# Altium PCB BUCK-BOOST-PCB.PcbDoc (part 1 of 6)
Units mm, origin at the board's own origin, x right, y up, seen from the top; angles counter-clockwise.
Board outline 99.9 x 67.48 mm, 4 copper layers (Top Layer, POWER, GND, Bottom Layer); 181 components, 110 nets, 560 pads, 389 vias.
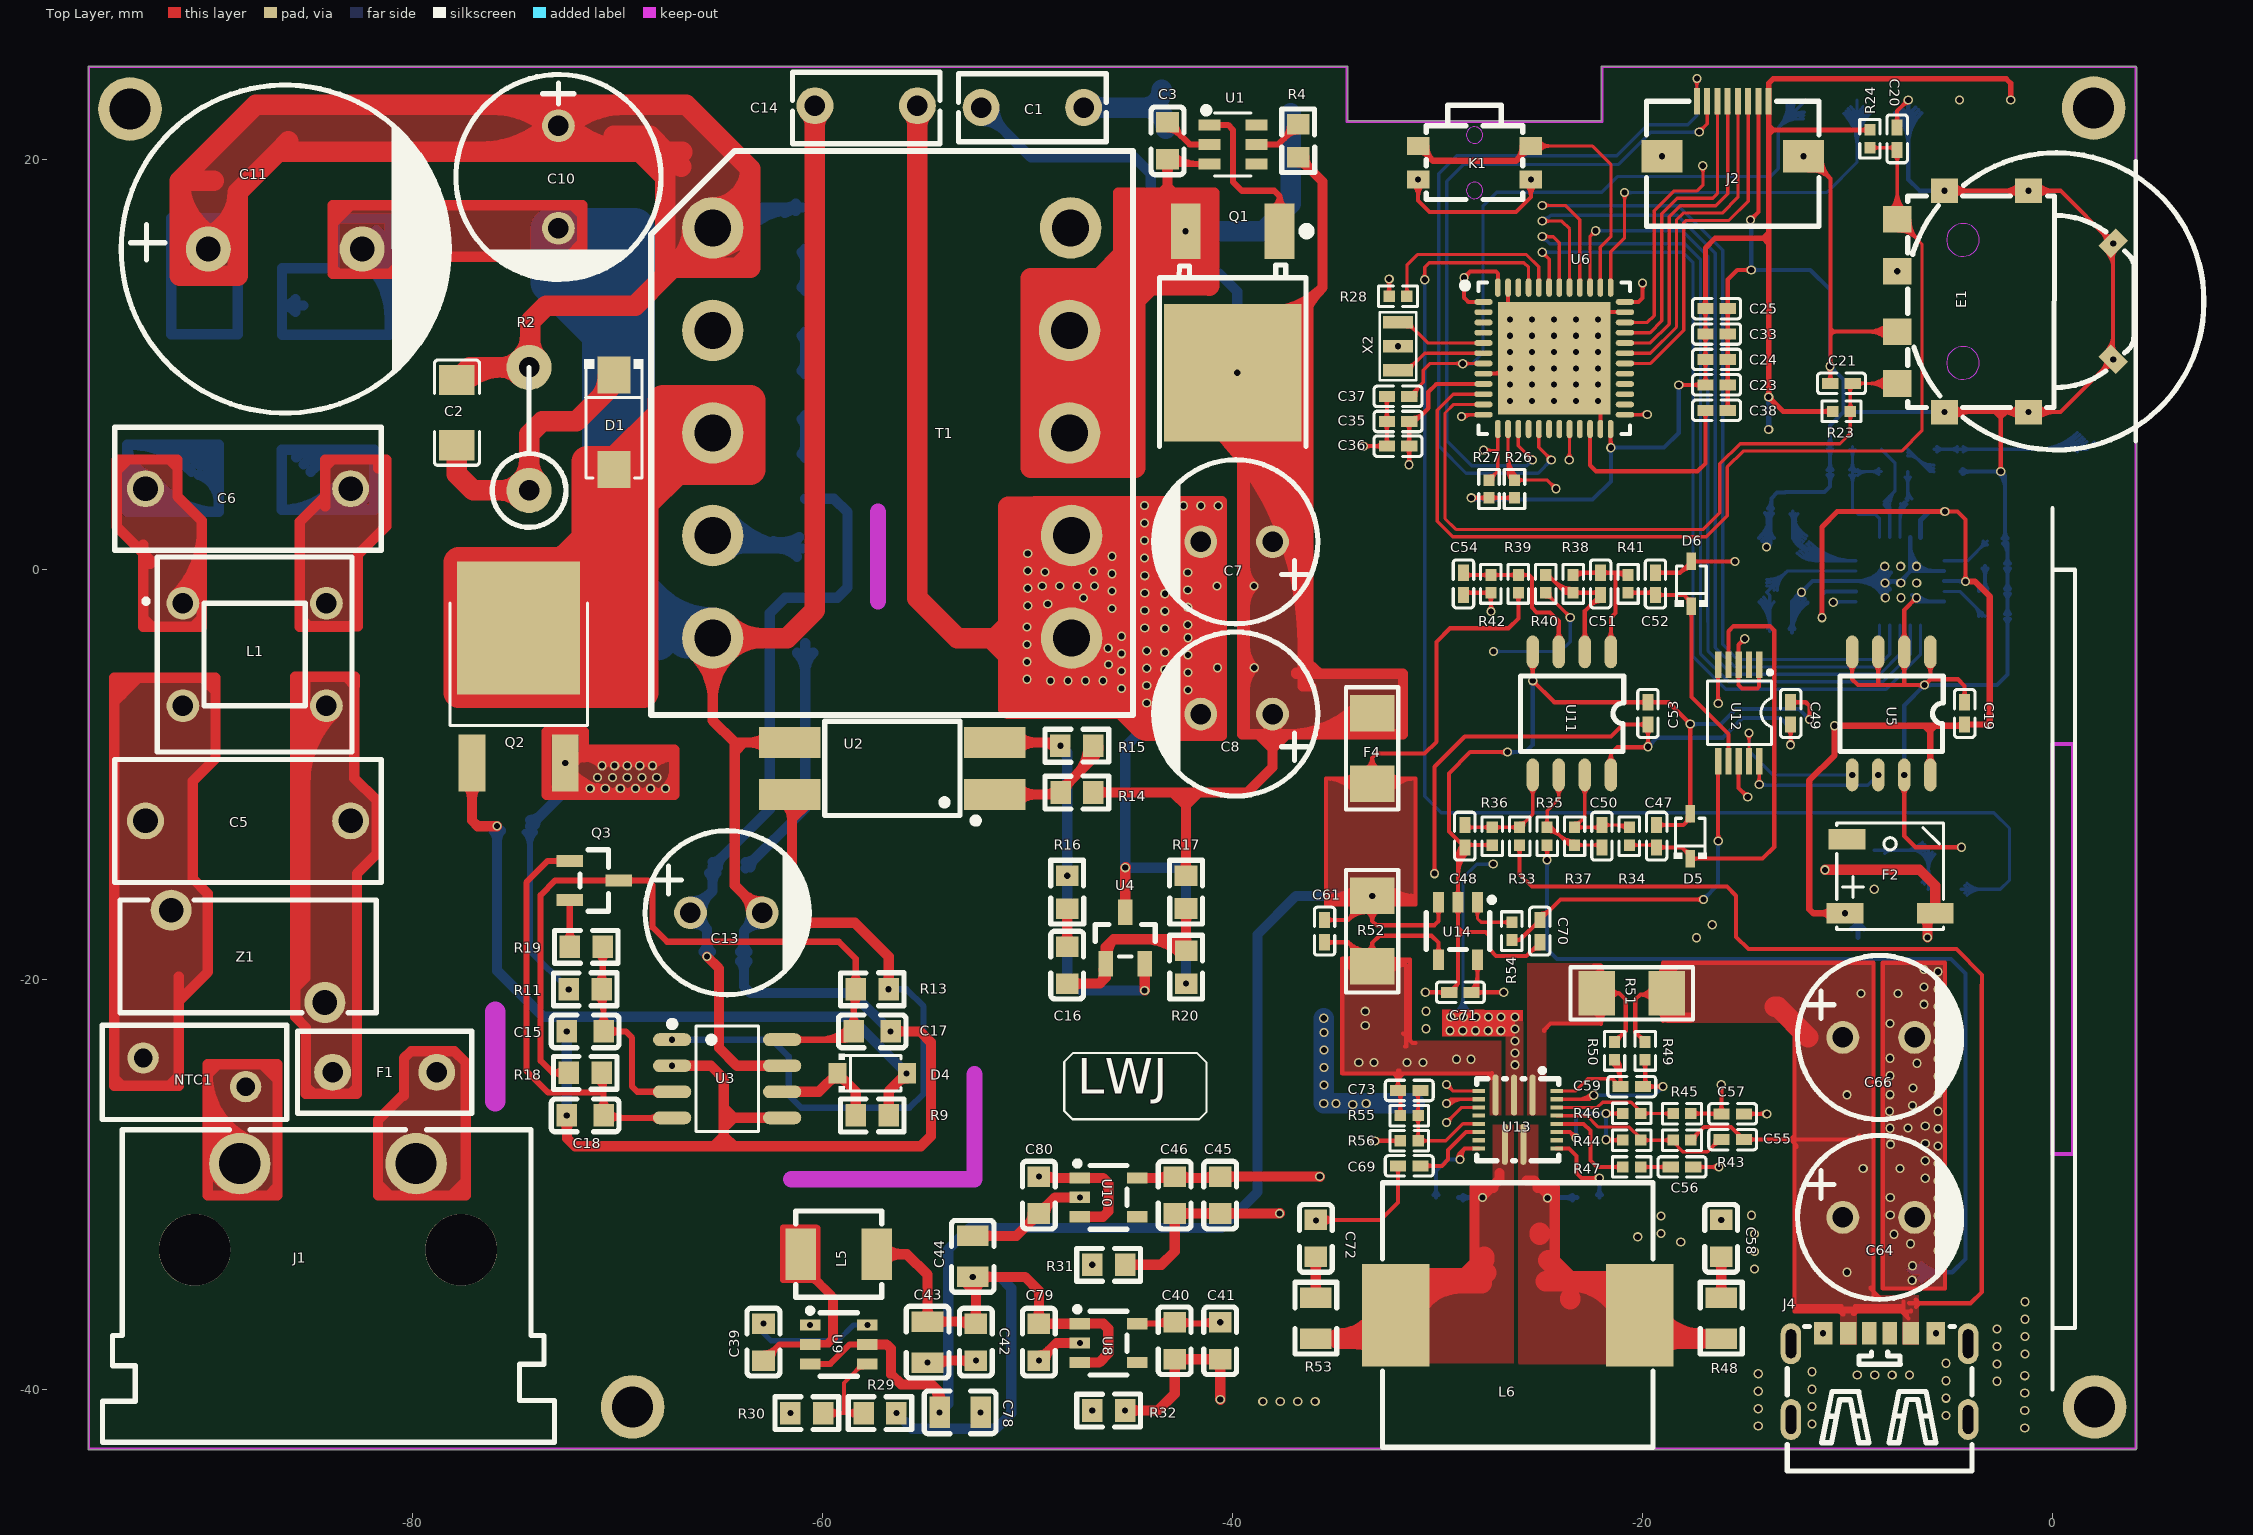
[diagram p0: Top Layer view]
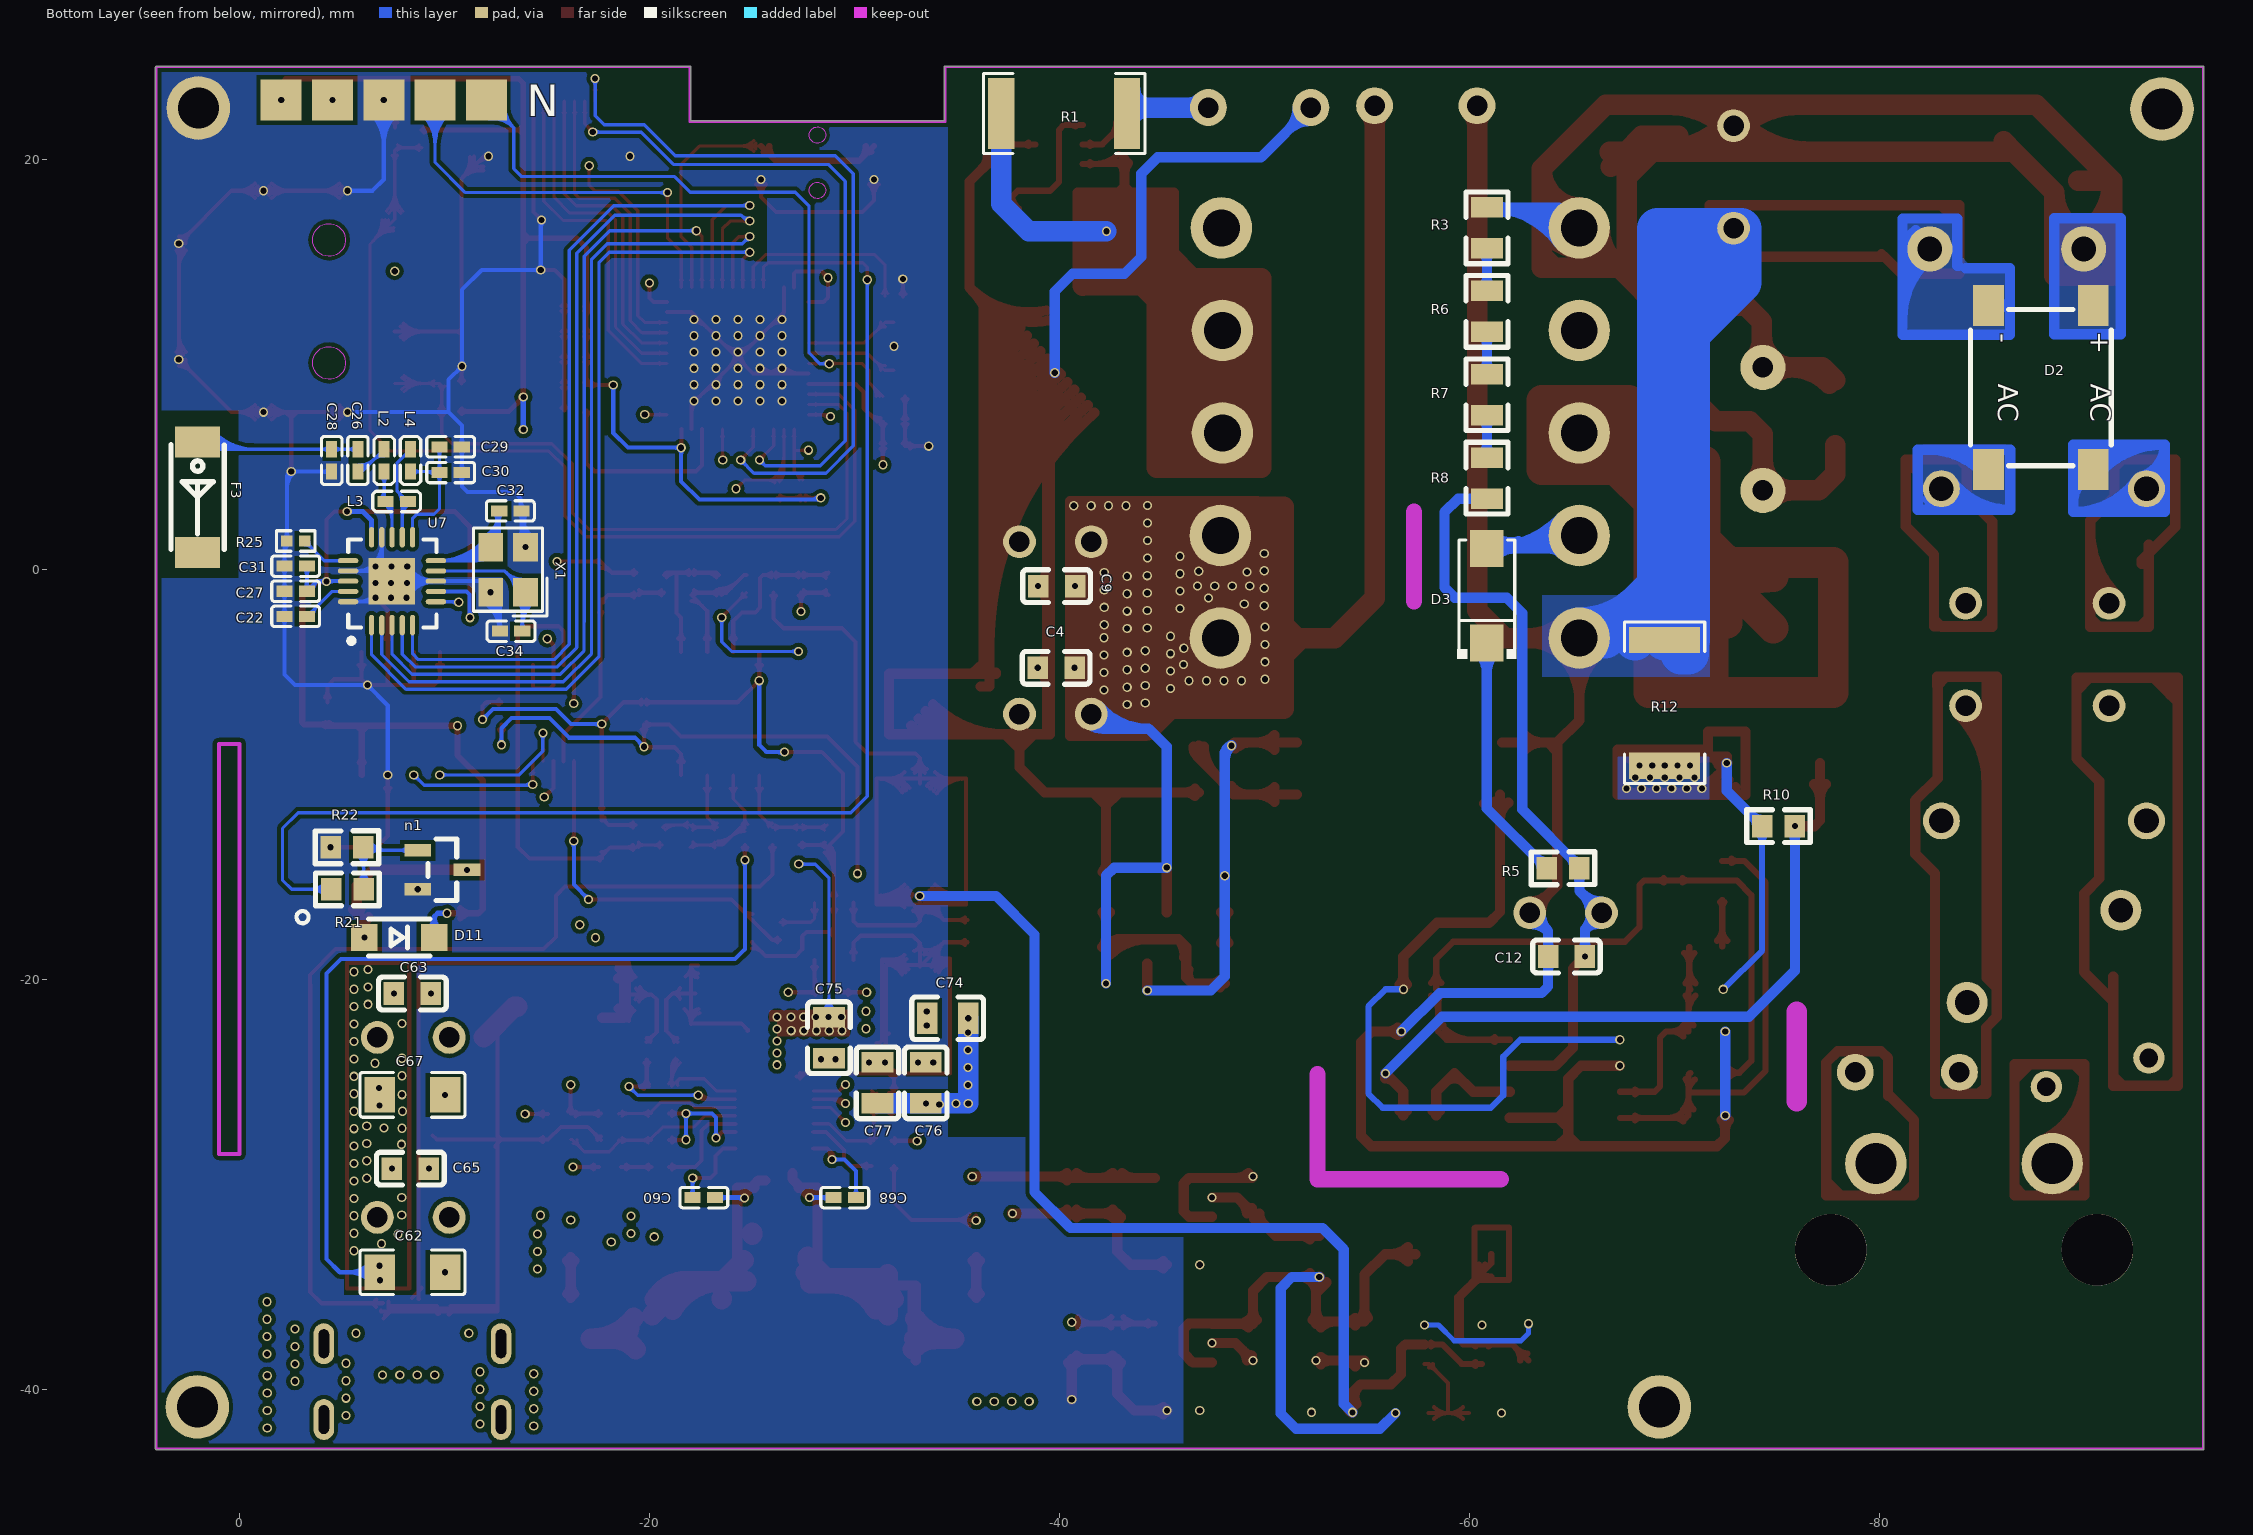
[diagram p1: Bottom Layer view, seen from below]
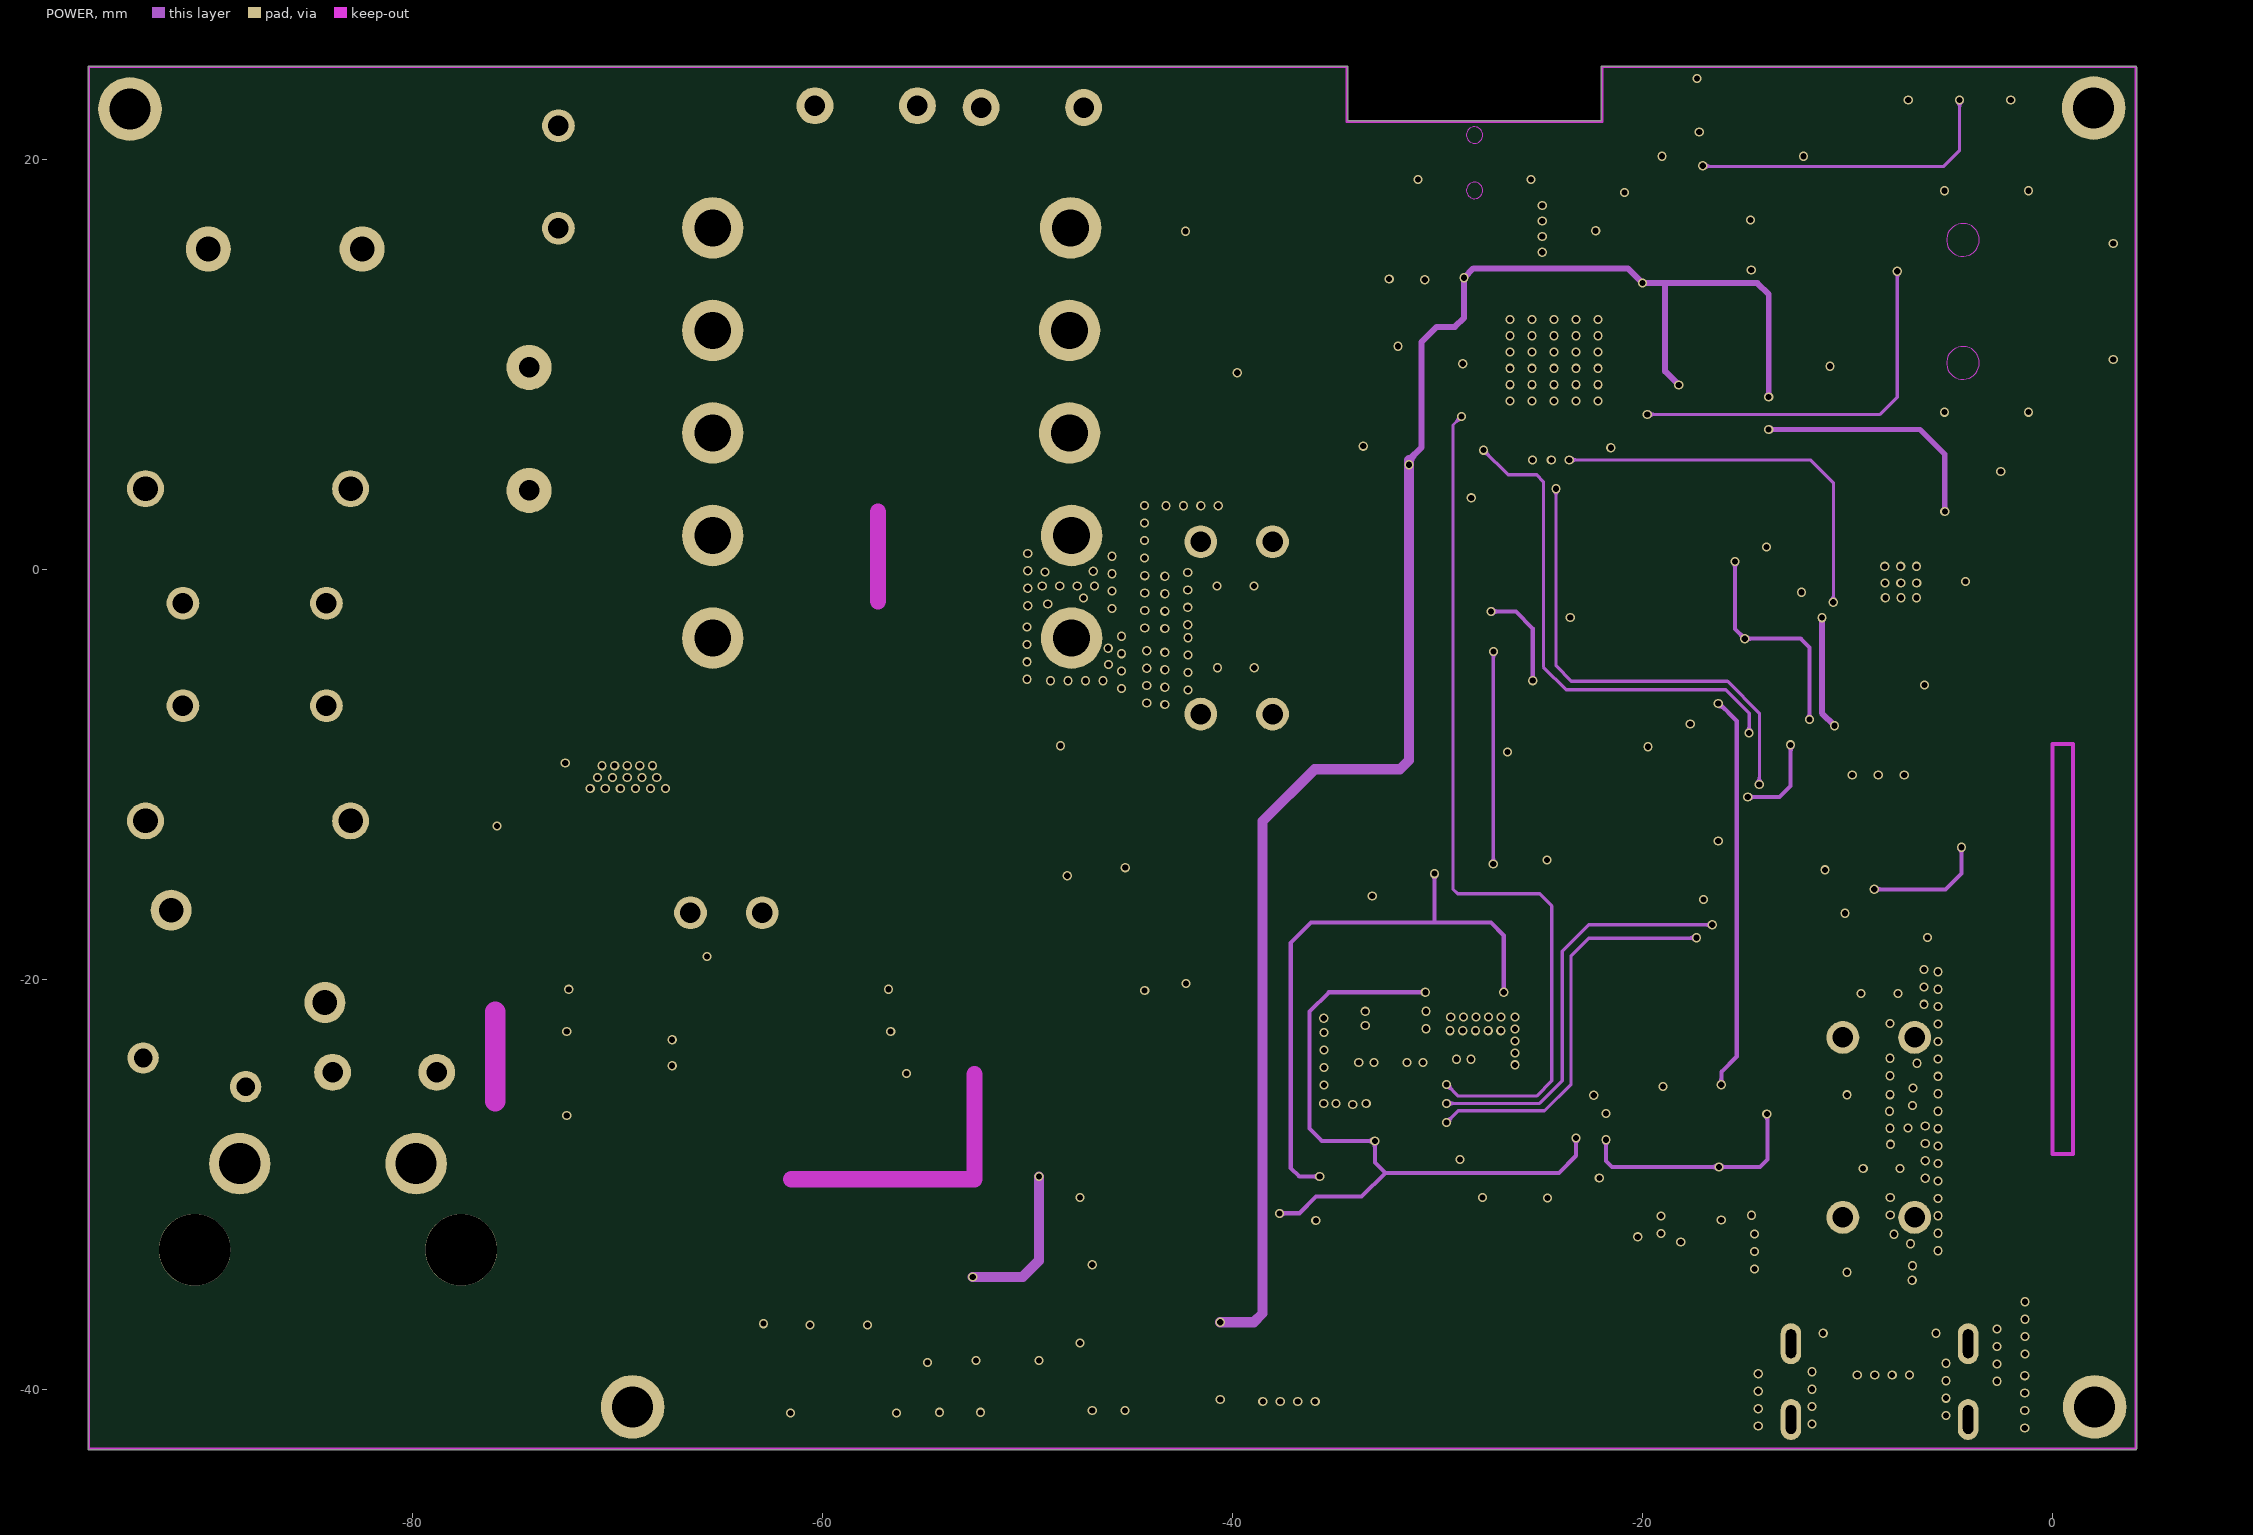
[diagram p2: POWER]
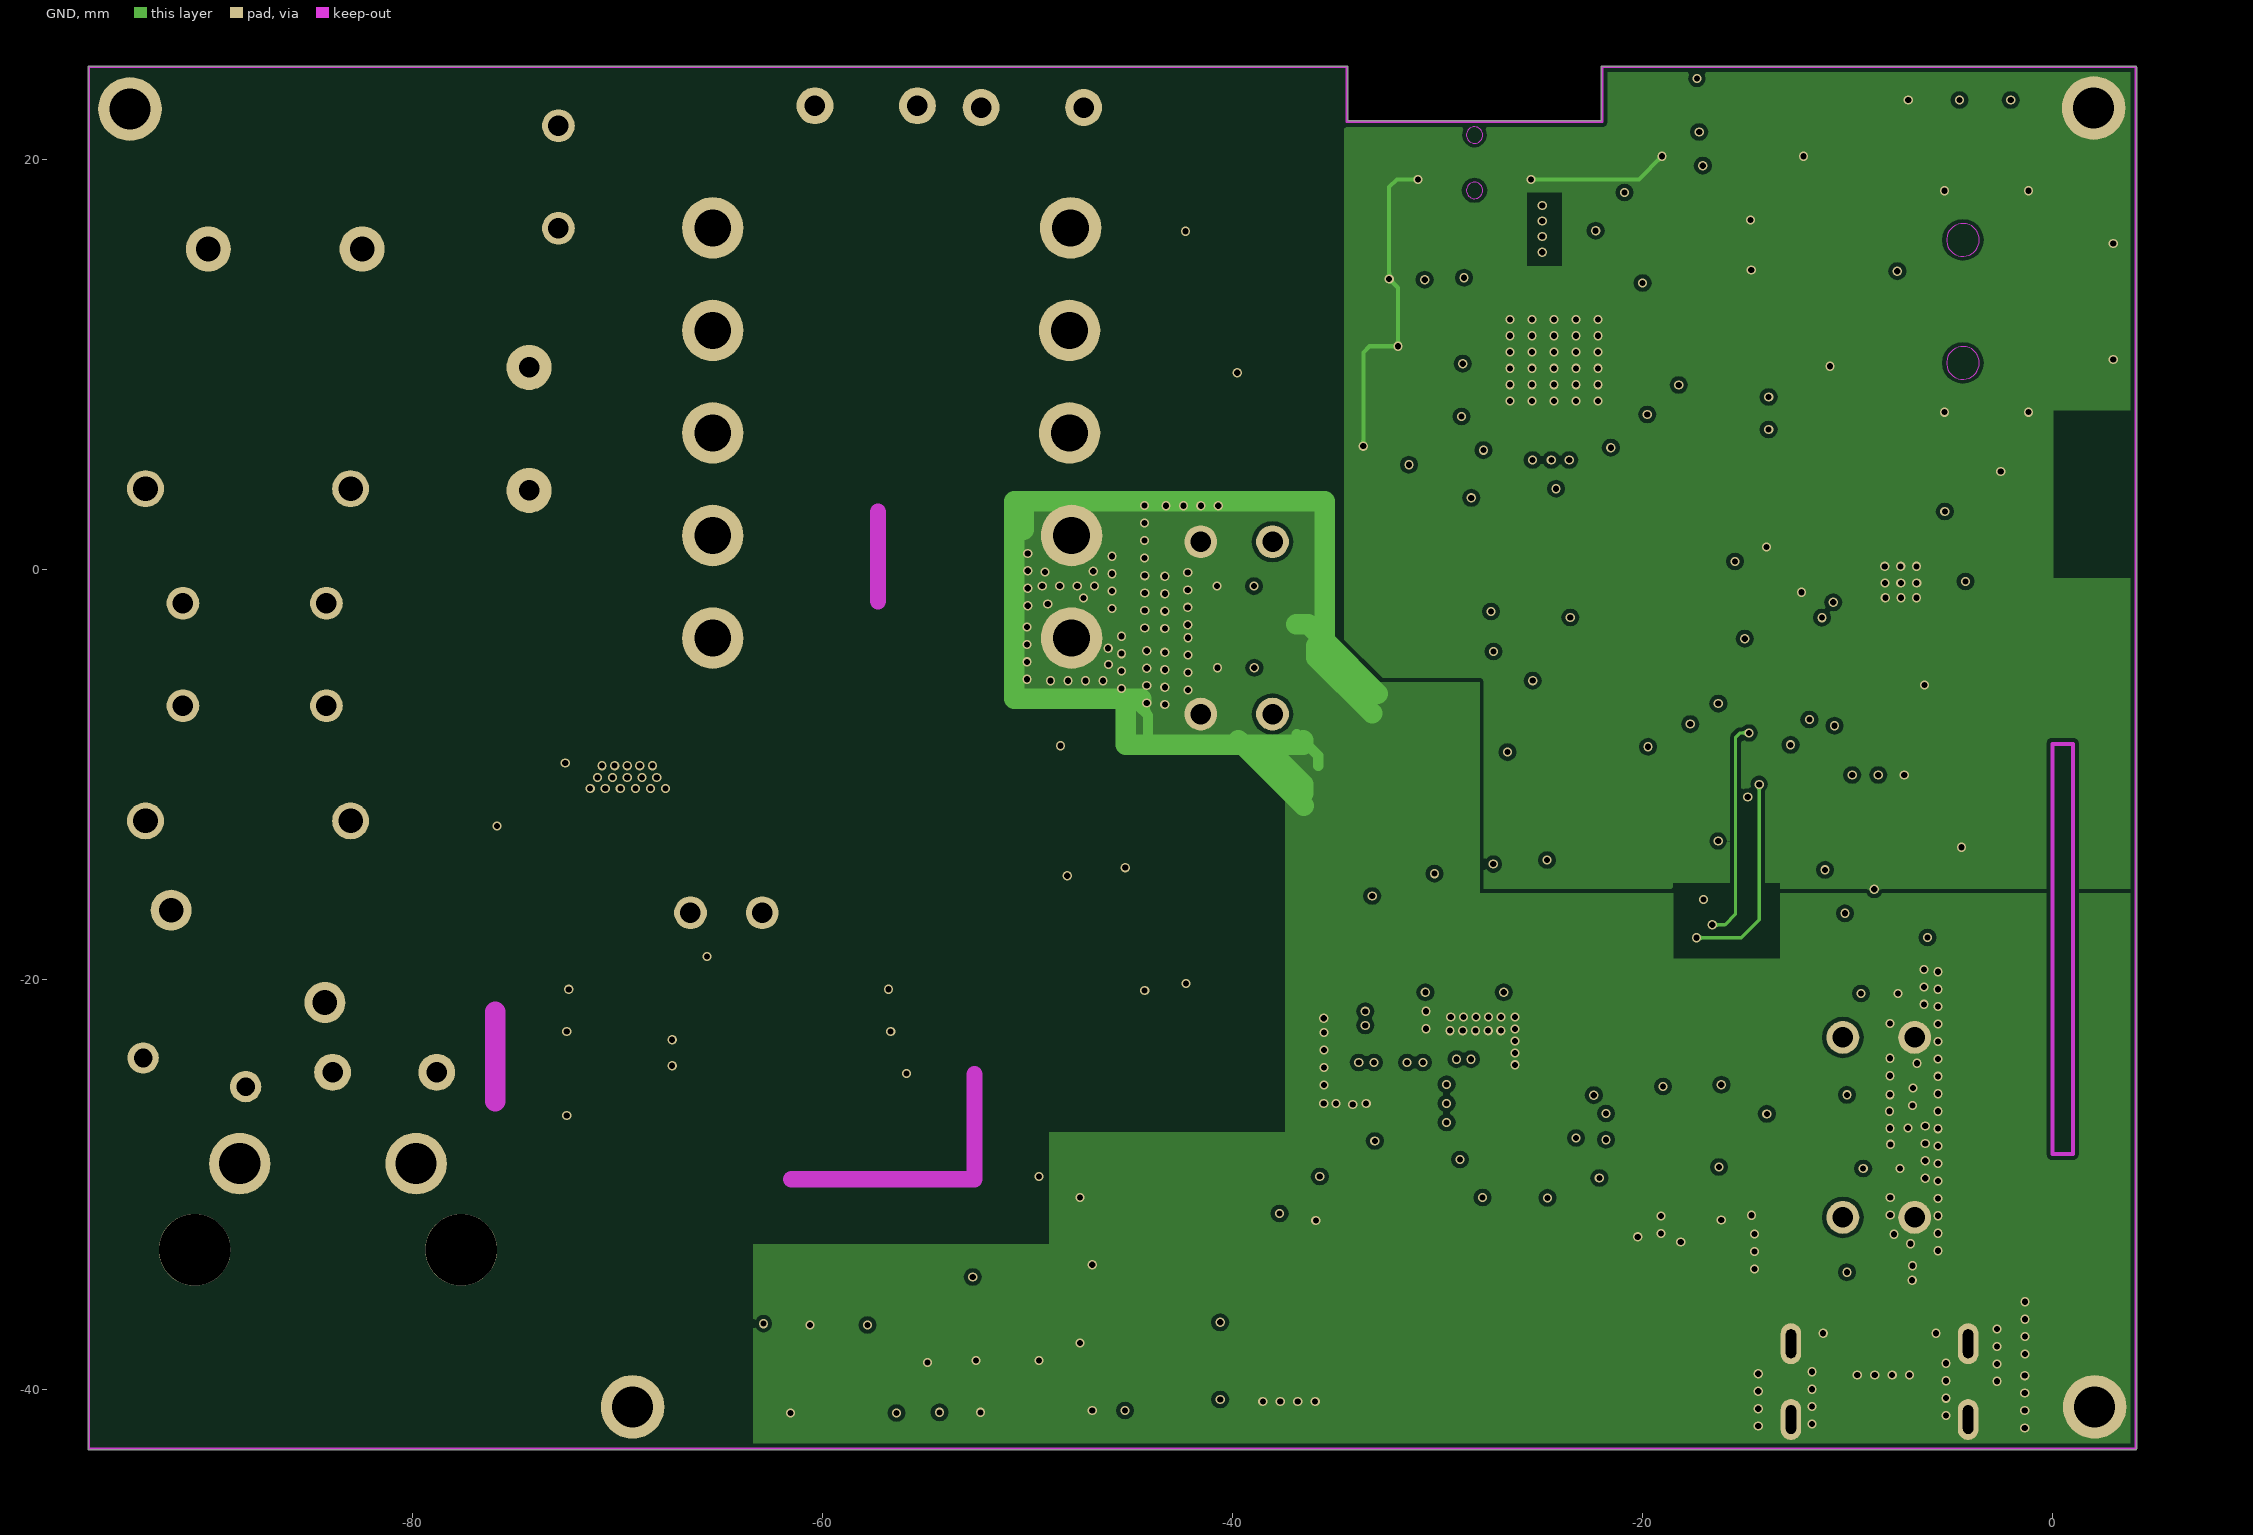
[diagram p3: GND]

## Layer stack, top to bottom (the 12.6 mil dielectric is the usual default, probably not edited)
Top Layer: signal copper 0.0356
Dielectric: core 0.32, FR-4, Dk 4.8
POWER: signal copper 0.0356
Dielectric: prepreg 0.32, FR-4, Dk 4.8
GND: signal copper 0.0356
Dielectric: core 0.32, FR-4, Dk 4.8
Bottom Layer: signal copper 0.0356

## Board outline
-95.799,-42.868 -95.799,24.512 cw(c-95.749,24.512) -95.738,24.561 -34.418,24.561 cw(c-34.418,24.511) -34.368,24.511 -34.368,21.896 -22.002,21.896 -22.002,24.511 cw(c-21.951,24.511) -21.951,24.561 4.041,24.561 cw(c4.053,24.512) 4.103,24.512 4.103,-42.868 cw(c4.053,-42.868) 4.041,-42.917 -95.738,-42.917 cw(c-95.749,-42.868)

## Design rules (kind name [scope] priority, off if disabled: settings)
Clearance [All] p1: gap=0.2
ComponentClearance [All] p1 off: gap=0.254 collisioncheckmode=3 verticalgap=0.254 showdistances=FALSE
PolygonConnect [All] p1: connectstyle=Direct reliefconductorwidth=0.254 reliefentries=4 polygonreliefangle="90 Angle" airgapwidth=0.254
RoutingVias [All] p1: holewidth=0.711 width=1.27 viastyle="Through Hole" minholewidth=0.711 minwidth=1.27 maxholewidth=0.711 maxwidth=1.27
SolderMaskExpansion [All] p1: expansion=0.102
Width [All] p1: maxlimit=2 minlimit=0.16 preferedwidth=1
27 further rules are at their usual default settings.

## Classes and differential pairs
component class FLYBACK: C1 C2 C3 C4 C5 C6 C7 C8 C9 C10 C11 C12 C13 C14 C15 C16 C17 C18 D1 D2 D3 D4 F1 J1 L1 NTC1 Q1 Q2 Q3 R1 R2 R3 R4 R5 R6 R7 R8 R9 R10 R11 R12 R13 R14 R15 R16 R17 R18 R19 R20 T1 U1 U2 U3 U4 Z1
component class MCU: C19 C20 C21 C22 C23 C24 C25 C26 C27 C28 C29 C30 C31 C32 C33 C34 C35 C36 C37 C38 D11 E1 F2 F3 J2 K1 L2 L3 L4 n1 R21 R22 R23 R24 R25 R26 R27 R28 U5 U6 U7 X1 X2
component class POWER: 1 C39 C40 C41 C42 C43 C44 C45 C46 C78 C79 C80 F4 L5 R29 R30 R31 R32 U8 U9 U10
component class ADC: C47 C48 C49 C50 C51 C52 C53 C54 D5 D6 R33 R34 R35 R36 R37 R38 R39 R40 R41 R42 U11 U12
component class SC8721: C55 C56 C57 C58 C59 C60 C61 C62 C63 C64 C65 C66 C67 C68 C69 C70 C71 C72 C73 C74 C75 C76 C77 J4 L6 R43 R44 R45 R46 R47 R48 R49 R50 R51 R52 R53 R54 R55 R56 U13 U14

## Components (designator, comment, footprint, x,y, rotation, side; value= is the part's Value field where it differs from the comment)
C1 "222 1KV" CBB-5.0 -52.221,22.342 r0 top
C2 "472 1KV" C1206 -77.813,6.095 r90 top
C3 "0.1uf" C0603 -43.156,20.019 r90 top
C4 "0.1uf" C0603 -38.924,-4.78 r180 bottom
C5 "0.22uf" P10MM -88.099,-12.097 r0 top
C6 "0.22uf" P10MM -87.904,3.802 r180 top
C7 "50V 470uf" 8*12mm -39.23,1.135 r180 top
C8 "50V 470uf" 8*12mm -39.23,-7.264 r180 top
C9 "0.1uf" C0603 -38.943,-0.797 r180 bottom
C10 "450V120UF" "400V 22UF 10*14" -72.38,21.146 r270 top
C11 "450V120UF" 16*20 -89.896,15.668 r0 top locked
C12 "10uf" C0603 -65.616,-18.861 r0 bottom
C13 "50V100UF" 8*12mm -65.228,-16.501 r0 top
C14 "10nf 1KV" CBB-5.0 -55.378,22.833 r180 top
C15 "220pf" C0603 -72.46,-22.515 r0 top
C16 "0.1uf" C0603 -48.049,-20.18 r90 top
C17 "0.1uf" C0603 -56.66,-22.515 r180 top
C18 "1000PF" C0603 -72.46,-26.613 r0 top
C19 "10uF" C0402 -4.279,-7.55 r90 top
C20 "10uF" C0402 -7.569,20.473 r90 top
C21 "10uF" C0402 -9.741,9.09 r180 top
C22 "33nf" C0402 -2.189,-2.273 r180 bottom
C23 "104" "C0402 - duplicate" -16.453,9.195 r180 top
C24 "104" "C0402 - duplicate" -16.453,10.435 r180 top
C25 "104" "C0402 - duplicate" -16.453,12.915 r180 top
C26 "1.5pf" C0402 -5.771,4.788 r90 bottom
C27 "104" C0402 -2.189,-1.047 r180 bottom
C28 "1pf" C0402 -4.489,4.788 r90 bottom
C29 "2.2nf" C0402 -9.749,5.995 r180 bottom
C30 "4.7pf" C0402 -9.749,4.74 r180 bottom
C31 "104" C0402 -2.189,0.178 r180 bottom
C32 "22pf" C0402 -12.66,2.87 r180 bottom
C33 "10uf" "C0402 - duplicate" -16.301,11.32 r0 top
C34 "22pf" C0402 -13.785,-2.995 r0 bottom
C35 "10uf" "C0402 - duplicate" -31.991,7.411 r180 top
C36 "10uf" "C0402 - duplicate" -31.991,6.207 r180 top
C37 "104" "C0402 - duplicate" -31.838,8.278 r0 top
C38 "4.7uf" "C0402 - duplicate" -16.301,7.6 r0 top
C39 "0.1uf" C0603 -62.862,-36.768 r270 top
C40 "0.1uf" C0603 -42.807,-36.702 r270 top
C41 "0.1uf" C0603 -40.587,-36.702 r270 top
C42 "0.1uf" C0603 -52.503,-36.77 r270 top
C43 "10uf" C0805 -54.86,-36.668 r270 top
C44 "10uf" C0805 -52.657,-34.489 r90 top
C45 "10uf" C0603 -40.587,-31.396 r90 top
C46 "10uf" C0603 -42.807,-31.396 r90 top
C47 "4.7uf" C0402 -19.301,-12.448 r270 top
C48 "0.1uf" C0402 -28.656,-13.539 r90 top
C49 "10uF" C0402 -12.766,-7.55 r90 top
C50 "330pf" C0402 -21.968,-12.448 r270 top
C51 "330pf" C0402 -22.034,-0.143 r270 top
C52 "4.7uf" C0402 -19.359,-1.234 r90 top
C53 "0.1uf" C0402 -19.726,-7.55 r90 top
C54 "0.1uf" C0402 -28.722,-1.234 r90 top
C55 "1n" C0402 -16.138,-27.791 r0 top
C56 "1n" C0402 -18.61,-29.125 r0 top
C57 "1n" C0402 -15.048,-26.537 r180 top
C58 "1n" C0603 -16.151,-33.511 r90 top
C59 "1n" C0402 -21.06,-25.207 r0 top
C60 "0.1u" C0402 -23.185,-30.621 r0 bottom
C61 "0.1uf" C0402 -35.496,-18.169 r90 top
C62 "1n" C1206 -9.997,-34.261 r0 bottom
C63 "1n" C0603 -9.33,-20.667 r0 bottom
C64 "50V 470uf" 8*12mm -9.024,-31.357 r0 top
C65 "22uf" C0603 -7.429,-29.204 r180 bottom
C66 "50V 470uf" 8*12mm -9.024,-22.582 r0 top
C67 "22uf" C1206 -6.862,-25.609 r180 bottom
C68 "0.1u" C0402 -28.969,-30.621 r180 bottom
C69 "2.2uf" C0402 -31.913,-29.074 r0 top
C70 "10uF" C0402 -25,-17.079 r270 top
C71 "10uF" "C0402 - duplicate" -28.799,-20.785 r0 top
C72 "1n" C0603 -35.923,-33.511 r90 top
C73 "1n" C0402 -30.822,-25.396 r180 top
C74 "22uf" C0805 -35.537,-21.876 r0 bottom
C75 "22uf" C0805 -28.743,-21.822 r270 bottom
C76 "22uf" C0805 -33.468,-26.029 r90 bottom
C77 "22uf" C0805 -31.11,-26.029 r90 bottom
C78 "22uf" C0805 -54.272,-41.095 r0 top
C79 "10uf" C0603 -49.428,-36.77 r270 top
C80 "10uf" C0603 -49.428,-29.595 r270 top
D1 "US1M" US1M -70.131,9.469 r270 top
D2 "UMSB40M" UMSB40M -88.028,8.452 r270 bottom
D3 "US1M" US1M -60.803,-3.541 r90 bottom
D4 "1N4148" 1N4148 -57.475,-24.678 r0 top
D5 "CESD3V3D3" SOD-323 -17.713,-12.988 r270 top
D6 "CESD3V3D3" SOD-323 -17.661,-0.683 r270 top
D11 "1N4007" SOD-123 -9.487,-17.937 r0 bottom
E1 "SIQ-02FVS3" SIQ-02FVS3 -1.562,13.164 r270 top locked
F1 "SQT6.30M 3.15A" SQT6.30M -83.879,-24.484 r0 top
F2 "MLT5020" MLT5020 -10.117,-16.755 r270 top
F3 "ANT" AN2051 2.303,3.254 r270 bottom
F4 "5A" R1206 -33.048,-8.932 r90 top
J1 "" "AC- RT-C08-F2-WH" -88.602,-32.852 r0 top
J2 "FPC-8P" FPC-8P -15.43,20.198 r180 top
J4 "TYPE-C" TYPEC-8A -8.941,-39.386 r0 top
K1 "中龟按键" TS-1186F-C-A -27.958,19.933 r0 top locked
L1 "EE8.3-5mH" EE8.3-5mH -87.631,-4.172 r270 top
L2 "3.9nh" L0402 -7.068,5.307 r90 bottom
L3 "8.2nh" L0402 -7.687,3.346 r0 bottom
L4 "2.7nh" L0402 -8.317,5.359 r270 bottom
L5 "4.7uh" L-0420 -61.016,-33.379 r0 top
L6 "10uh 6A" 2.2uh -24.478,-37.034 r180 top
n1 "NPN（9014）" SOT-23 -8.689,-13.684 r0 bottom
NTC1 "NTC 3950" NTC-5.0 -88.178,-25.17 r180 top
Q1 "NCE0130KA" NCE0130KA -41.76,10.697 r180 top
Q2 "IPD70R900P7S" IPD70R900P7S -74.804,-3.974 r90 top
Q3 "NPN（9014）" SOT-23 -72.315,-14.201 r180 top
R1 "47R 2W" 2512 -43.283,22.254 r0 bottom
R2 "16.8K" R1W -74.294,3.895 r90 top
R3 "30K" R0805 -60.834,16.689 r90 bottom
R4 "200R" R0603 -36.78,20.779 r90 top
R5 "22R" R0603 -64.404,-14.558 r180 bottom
R6 "30K" R0805 -60.834,12.62 r90 bottom
R7 "30K" R0805 -60.834,8.551 r90 bottom
R8 "30K" R0805 -60.834,4.482 r90 bottom
R9 "10R" R0603 -57.419,-26.613 r180 top
R10 "10K" R0603 -75.194,-12.503 r0 bottom
R11 "1k" R0603 -71.701,-20.463 r0 top
R12 "0.5R 2W" 2512 -69.501,-3.421 r270 bottom
R13 "2k" R0603 -57.419,-20.458 r180 top
R14 "220R" R0603 -47.436,-10.861 r180 top
R15 "2K" R0603 -47.718,-8.583 r0 top
R16 "1K" R0603 -48.047,-15.862 r90 top
R17 "4.2K" R0603 -42.257,-15.58 r270 top
R18 "15.4K" R0603 -71.419,-24.536 r180 top
R19 "1K" R0603 -71.643,-18.392 r0 top
R20 "1K" R0603 -42.252,-19.52 r90 top
R21 "1k" R0603 -5.398,-15.585 r0 bottom
R22 "1k" R0603 -5.378,-13.533 r0 bottom
R23 "10k" R0402 -10.133,7.419 r180 top
R24 "10k" R0402 -9.202,20.866 r90 top
R25 "22k" R0402 -2.887,1.099 r0 bottom
R26 "10k" R0402 -25.93,4.094 r270 top
R27 "10K" R0402 -27.174,4.094 r270 top
R28 "10K" R0402 -32.067,13.644 r0 top
R29 "33.2K" R0603 -57.036,-41.129 r180 top
R30 "10K" R0603 -60.606,-41.129 r180 top
R31 "0R" R0603 -45.89,-33.897 r180 top
R32 "0R" R0603 -45.89,-41.004 r180 top
R33 "68K" R0402 -25.676,-12.841 r270 top
R34 "1K" R0402 -20.935,-13.146 r90 top
R35 "68K" R0402 -24.338,-12.841 r270 top
R36 "10K" R0402 -27.623,-13.146 r90 top
R37 "10K" R0402 -23.61,-13.146 r90 top
R38 "10K" R0402 -23.067,-0.536 r270 top
R39 "68K" R0402 -25.742,-0.536 r270 top
R40 "68K" R0402 -24.404,-0.536 r270 top
R41 "1K" R0402 -21.001,-0.841 r90 top
R42 "10K" R0402 -27.689,-0.841 r90 top
R43 "0R" R0402 -17.912,-28.125 r180 top
R44 "0R" R0402 -20.363,-28.125 r180 top
R45 "0R" R0402 -18.217,-26.223 r0 top
R46 "0R" R0402 -20.668,-26.21 r0 top
R47 "0R" R0402 -20.363,-29.43 r180 top
R48 "0R" R0805 -16.151,-36.518 r270 top
R49 "0R" R0402 -20.164,-23.617 r90 top
R50 "0R" R0402 -21.659,-23.617 r90 top
R51 "0.01R" R1206 -20.731,-20.783 r0 top
R52 "0.01R" R1206 -33.048,-17.84 r90 top
R53 "0R" R0805 -35.923,-36.487 r90 top
R54 "1K" R0402 -26.055,-17.471 r270 top
R55 "0R" R0402 -31.52,-26.317 r0 top
R56 "0R" R0402 -31.215,-28.153 r180 top
T1 "EC25/30" EE28 -65.336,16.671 r0 top
U1 "RM3430T" RM3430T -39.996,20.972 r270 top
U2 "PC817" PC817SMD -55.206,-9.906 r180 top
U3 "UC3843" UC3845 -64.431,-24.926 r0 top
U4 "TL431" tl431 -45.394,-17.926 r270 top
U5 "24C02" SOP-8 -5.954,-4.006 r180 top
U6 "STM32F411CEU6" UFQFPN-48 -25.084,11.33 r270 top locked
U7 "NRF24L0" QFN20 -6.434,-2.7 r90 bottom locked
U8 "ME6211" SOT-23-5 -46.282,-37.523 r180 top
U9 "TPS562201DDCR" SOT-23-6 -59.036,-37.488 r180 top
U10 "ME6211" SOT-23-5 -46.282,-30.416 r180 top
U11 "SGM8552" SOP-8 -21.535,-4.006 r180 top
U12 "ADS1115" MSOP-10 -15.399,-7.018 r180 top
U13 "SC8721" QFN-21(4x4) -26.078,-26.34 r180 top
U14 "INA180A2" SOT-23-5 -28.796,-17.373 r90 top
X1 "16MHZ" SMD3225 -13.929,-0.961 r90 bottom
X2 "cstce8m" CSTE8M -31.914,12.07 r270 top
Z1 "14D681" CNR-10D561KBTSA -86.884,-19.11 r180 top

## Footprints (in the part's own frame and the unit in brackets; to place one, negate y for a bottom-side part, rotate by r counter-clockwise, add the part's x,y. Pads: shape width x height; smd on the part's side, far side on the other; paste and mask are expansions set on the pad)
1N4148 [mm]
  rect 0.88x0.99 smd: 1(-1.778,0.127) 2(1.607,0.127)
  silkscreen extent -1.72,-0.82 1.32,1.07
2.2uh [mm]
  rect 3.3x5 smd: 1(-4.35,-0.686) 2(7.55,-0.686)
  silkscreen extent -5,-7.14 8.2,5.76
8*12mm [mm]
  round 1.6 hole 1: 1(-1.194,-0.229) 2(2.306,-0.229)
  silkscreen extent -3.41,-4.23 4.59,3.77
16*20 [mm]
  round 2.2 hole 1.2 mask+0.051: 1(-0.041,-0.026) 2(7.458,-0.025)
  silkscreen extent -4.29,-8.02 11.72,7.97
"400V 22UF 10*14" [mil]
  round 63 hole 39.4 mask+2: 1(-20,-19) 2(176.8,-19)
  silkscreen extent -118,-216 278,178
2512 [mm]
  rect 1.283x3.456 smd: 1(0,0) 2(6.133,0)
  silkscreen extent -0.87,-1.96 7,1.96
"AC- RT-C08-F2-WH" [mm]
  round 3 hole 2: 1(8.796,3.886) 2(0.196,3.886)
  round 3.5 hole 3.5 unplated: ""(-2.004,-0.314) ""(10.996,-0.314)
  silkscreen extent -6.5,-9.7 15.54,5.54
AN2051 [mil]
  rect 59.1x86.6 smd mask+2: 1(-117,10) 2(94.8,10)
  silkscreen extent -112,-41 89,61
C0402 [mm]
  rect 0.79x0.54 smd: 1(0,0) 2(1.09,0)
  silkscreen extent -0.62,-0.5 1.71,0.5
"C0402 - duplicate" [mm]
  rect 0.79x0.54 smd: 1(-0.621,0.178) 2(0.469,0.178)
  silkscreen extent -1.24,-0.32 1.09,0.68
C0603 [mm] "C0603"
  rect 1.001x1.102 smd: 1(0,0) 2(1.801,0)
  silkscreen extent -0.75,-0.8 2.55,0.8
C0805 [mil]
  rect 39.4x61 smd: 1(0,0)
  rect 39.3x61 smd: 2(78.7,0)
  silkscreen extent -30,-41 108,41
C1206 [mm]
  rect 1.485x1.728 smd: 1(-0.025,0) 2(3.16,0)
  silkscreen extent -1,-1.09 4.13,1.09
CBB-5.0 [mm]
  round 1.8 hole 1: 1(-0.025,0.203) 2(4.973,0.203)
  silkscreen extent -1.13,-1.46 6.07,1.85
CNR-10D561KBTSA [mm]
  round 1.999 hole 1.199 mask+0.051: 1(-2.631,1.996) 2(4.867,-2.504)
  silkscreen extent -5.13,-3 7.37,2.5
CSTE8M [mm]
  rect 0.6x1.45 smd: 1(0,0) 2(2.337,0) 3(1.168,0)
  silkscreen extent -0.48,-0.89 2.82,0.89, body extent -0.44,-0.76 2.76,0.76, height 0.7
EE8.3-5mH [mm]
  round 1.6 hole 1 mask+0.05: 1(-2.54,-3.546) 2(2.46,-3.546) 3(2.46,3.454) 4(-2.54,3.454)
  silkscreen extent -4.79,-5.45 4.71,4.7
EE28 [mm]
  round 3 hole 1.8: 1(0,0) 2(0,-5) 3(0,-10) 4(0,-15) 5(0,-20) 6(17.5,-20) 7(17.5,-15) 8(17.4,-10) 9(17.4,-5) 10(17.45,0)
  silkscreen extent -3,-23.75 20.5,3.75
FPC-8P [mm]
  rect 0.3x1.3 smd paste+0 mask+0.05: 1(-1.593,-2.652) 2(-1.095,-2.65) 3(-0.593,-2.652) 4(-0.093,-2.652) 5(0.407,-2.652) 6(0.907,-2.652) 7(1.407,-2.652) 8(1.907,-2.652)
  rect 2x1.6 smd: 9(3.607,0.028) 10(-3.293,0.028)
  silkscreen extent -4.04,-2.65 4.36,3.45
IPD70R900P7S [mm]
  rect 2.8x1.3 smd mask+0.051: 1(-5.451,2.273) 3(-5.451,-2.273)
  rect 6.5x6 smd mask+0.051: 2(1.133,0)
  silkscreen extent -3.62,-3.35 2.35,3.34
L0402 [mm]
  rect 0.79x0.54 smd mask+0.051: 1(-0.519,0.016) 2(0.571,0.016)
  silkscreen extent -1.14,-0.48 1.19,0.51
L-0420 [mm]
  rect 1.5x2.5 smd: 1(-0.025,0) 2(3.674,0)
  silkscreen extent -0.28,-2.1 3.92,2.1
MLT5020 [mm]
  rect 1x1.8 smd: 1(0,0) 2(0,4.402) 3(-3.601,0.099)
  silkscreen extent -4.4,-0.4 0.8,4.8
MSOP-10 [mm]
  rect 0.3x1.3 smd paste+0 mask+0.015: 1(-1.099,-2.38) 2(-0.599,-2.38) 3(-0.099,-2.38) 4(0.401,-2.38) 5(0.901,-2.38)
  rect 0.3x1.3 smd paste+0 mask+0.051: 6(0.901,2.32) 7(0.401,2.32) 8(-0.099,2.32) 9(-0.599,2.32) 10(-1.099,2.32)
  silkscreen extent -1.72,-2.11 1.42,1.51
NCE0130KA [mil]
  rect 57.1x106.3 smd mask+2: 1(-160.2,-228.8) 3(20.2,-228.8)
  rect 263.8x263.8 smd mask+2: 2(-70,42.8)
  silkscreen extent -220,-237 70,184
NTC-5.0 [mil]
  round 60 hole 36: 1(-2.4,1.56) 2(194.4,-53.56)
  silkscreen extent -81,-117 273,65
P10MM [mm]
  round 1.8 hole 1.2: 1(-4.902,-0.152) 2(5.098,-0.152)
  silkscreen extent -6.4,-3.15 6.6,2.85
PC817SMD [mm]
  rect 3x1.5 smd mask+0.051: 1(-3.631,1.055) 2(-3.631,-1.485) 3(6.369,-1.485) 4(6.369,1.055)
  silkscreen extent -2.84,-2.51 4.67,2.48
QFN20 [mm]
  oval 1x0.25 smd: 1(0,0) 2(0,-0.5) 3(0,-1) 4(0,-1.5) 5(0,-2) 11(4.286,-2) 12(4.286,-1.5) 13(4.286,-1) 14(4.286,-0.5) 15(4.286,0)
  oval 0.25x1 smd: 6(1.143,-3.143) 7(1.643,-3.143) 8(2.143,-3.143) 9(2.643,-3.143) 10(3.143,-3.143) 16(3.143,1.143) 17(2.643,1.143) 18(2.143,1.143) 19(1.643,1.143) 20(1.143,1.143)
  rect 2.261x2.261 smd: 21(2.134,-0.991)
  silkscreen extent -0.89,-3.17 4.18,1.13, body extent 0.03,-3.02 4.03,0.98, height 0.9
QFN-21(4x4) [mm]
  oval 0.3x2 smd paste+0 mask+0.051: 1(-0.725,-0.717) 2(0.175,-0.717) 3(1.075,-0.717) 12(0.625,1.683) 13(-0.275,1.683)
  rect 0.6x0.2 smd paste+0 mask+0.051: 4(1.9,-0.917) 5(1.9,-0.517) 6(1.9,-0.117) 7(1.9,0.283) 8(1.9,0.683) 9(1.9,1.083) 10(1.9,1.483) 11(1.9,1.883) 14(-1.9,1.883) 15(-1.9,1.483) 16(-1.9,1.083) 17(-1.9,0.683) 18(-1.9,0.283) 19(-1.9,-0.117) 20(-1.9,-0.517) 21(-1.9,-0.917)
  silkscreen extent -2,-2.02 2,2.48
R1W [mm]
  round 2.2 hole 1: 1(-0.025,0) 2(5.975,0)
  silkscreen extent -1.82,-1.8 5.97,1.8
R0402 [mm]
  rect 0.566x0.54 smd: 1(-0.28,-0.305) 2(0.585,-0.305)
  silkscreen extent -0.79,-0.8 1.1,0.19
R0603 [mil]
  rect 39.4x43.4 smd: 1(-26,0) 2(37,0)
  silkscreen extent -56,-32 67,32
R0805 [mil]
  rect 39.4x61 smd: 1(-40,0)
  rect 39.3x61 smd: 2(38.7,0)
  silkscreen extent -70,-40 68,40
R1206 [mil]
  rect 70x85 smd: 1(76,5) 2(-59,5)
  silkscreen extent -109,-45 126,55
RM3430T [mil]
  rect 20.95x42.2 smd mask+2: 1(-28.4,-44.24) 2(9,-44.24) 3(46.4,-44.24) 4(46.4,46.24) 5(9,46.24) 6(-28.4,46.24)
  silkscreen extent -63,-56 70,36
SIQ-02FVS3 [mm]
  rect 1.2x1.3 smd mask+0.05: 1(5.476,-3.701) 2(5.476,0.399) 5(-5.324,0.399) 6(-5.324,-3.701)
  rect 0.85x1.2 smd rot 135 mask+0.05: 3(2.904,4.528)
  rect 0.85x1.2 smd rot 45 mask+0.05: 4(-2.752,4.528)
  rect 1.3x1.4 smd mask+0.05: A(-3.924,-6.001) B(4.076,-6.001) C(1.551,-6.001) S(-1.399,-6.001)
  Keep-Out Layer circle w0.005: c-2.924,-2.801 r0.8
  Keep-Out Layer circle w0.005: c3.076,-2.801 r0.8
  silkscreen extent -7.18,-5.5 7.32,8.95
SMD3225 [mm]
  rect 1.4x1.2 smd: 1(-0.135,-0.012) 2(2.065,-0.012) 3(2.065,1.688) 4(-0.135,1.688)
  silkscreen extent -1.29,-1.07 2.99,2.52
SOD-123 [mm]
  rect 1.3x1.3 smd: 1(0,0) 2(3.4,0)
  silkscreen extent 0.2,-0.9 3.2,0.9
SOD-323 [mm]
  rect 0.845x0.455 smd: 1(1.103,0.051) 2(-1.092,0.051)
  silkscreen extent -0.87,-0.75 1.11,0.85
SOP-8 [mm]
  oval 0.6x1.599 smd: 1(0,0) 2(1.27,0) 3(2.54,0) 4(3.81,0) 5(3.81,5.999) 6(2.54,5.999) 7(1.27,5.999) 8(0,5.999)
  silkscreen extent -0.64,1.17 4.4,4.85
SOT-23 [mm]
  rect 1.3x0.6 smd: 1(0,0) 2(0,1.9) 3(-2.4,0.95)
  silkscreen extent -1.9,-0.55 -0.5,2.45
SOT-23-5 [mm]
  rect 1x0.55 smd: 1(1.149,-0.757) 2(1.149,0.193) 3(1.149,1.143) 4(-1.651,1.143) 5(-1.651,-0.757)
  silkscreen extent -1.15,-1.58 1.4,1.74
SOT-23-6 [mm]
  rect 1x0.55 smd: 1(1.555,-0.655) 2(1.555,0.295) 3(1.555,1.245) 4(-1.245,1.245) 5(-1.245,0.295) 6(-1.245,-0.655)
  silkscreen extent -0.74,-1.48 1.68,1.84
SQT6.30M [mm]
  round 1.8 hole 1: 1(0,-0.025) 2(5.08,-0.025)
  silkscreen extent -1.71,-2.03 6.79,1.97
tl431 [mil]
  rect 49.2x27.6 smd: 1(50.4,-30.4) 2(50.4,44.4) 3(-48,7)
  silkscreen extent -24,-51 37,64
TS-1186F-C-A [mm]
  rect 1.1x0.875 smd paste+0 mask+0.051: 1(-2.977,0.733) 2(2.523,0.733) 3(-2.977,-0.893) 4(2.523,-0.893)
  Keep-Out Layer circle w0.005: c-0.227,1.27 r0.4
  Keep-Out Layer circle w0.005: c-0.227,-1.43 r0.4
  silkscreen extent -2.58,-1.88 2.12,2.72
TYPEC-8A [mm]
  oval 1x2 hole 0.5 slot 1.4 at 90 deg: 7(-3.809,-2.06) 7(-3.809,1.64) 7(4.831,-2.06) 7(4.831,1.64)
  rect 0.7x1.1 smd paste-100 mask+0.051: A5(0.011,2.15) B5(1.011,2.15)
  rect 0.8x1.1 smd paste-100 mask+0.051: A9(2.031,2.15) B9(-1.009,2.15)
  rect 0.9x1.1 smd paste-100 mask+0.051: A12(3.261,2.15) B12(-2.239,2.15)
  silkscreen extent -3.99,-4.56 5.01,2.48
UC3845 [mm]
  oval 1.865x0.63 smd mask+0.051: 1(-2.886,2.007) 2(-2.886,0.737) 3(-2.886,-0.533) 4(-2.886,-1.803) 5(2.479,-1.803) 6(2.479,-0.533) 7(2.479,0.737) 8(2.479,2.007)
  silkscreen extent -3.04,-2.47 1.32,2.92
UFQFPN-48 [mm]
  oval 0.28x0.9 smd: 1(-1.735,-2.662) 2(-1.234,-2.662) 3(-0.734,-2.662) 4(-0.234,-2.662) 5(0.267,-2.662) 6(0.767,-2.662) 7(1.265,-2.662) 8(1.765,-2.662) 9(2.266,-2.662) 10(2.766,-2.662) 11(3.267,-2.662) 12(3.767,-2.662) 25(3.767,4.237) 26(3.267,4.237) 27(2.766,4.237) 28(2.266,4.237) 29(1.765,4.237) 30(1.265,4.237) 31(0.767,4.237) 32(0.267,4.237) 33(-0.234,4.237) 34(-0.734,4.237) 35(-1.234,4.237) 36(-1.735,4.237)
  oval 0.9x0.28 smd: 13(4.465,-1.963) 14(4.465,-1.463) 15(4.465,-0.963) 16(4.465,-0.462) 17(4.465,0.038) 18(4.465,0.538) 19(4.465,1.036) 20(4.465,1.537) 21(4.465,2.037) 22(4.465,2.537) 23(4.465,3.038) 24(4.465,3.538) 37(-2.433,3.538) 38(-2.433,3.038) 39(-2.433,2.537) 40(-2.433,2.037) 41(-2.433,1.537) 42(-2.433,1.036) 43(-2.433,0.538) 44(-2.433,0.038) 45(-2.433,-0.462) 46(-2.433,-0.963) 47(-2.433,-1.463) 48(-2.433,-1.963)
  rect 5.5x5.5 smd: 49(1.016,0.787)
  silkscreen extent -2.68,-3.71 4.72,4.49
UMSB40M [mil]
  rect 78.7x59.1 smd mask+2: 1(-174.5,93.4) 2(-174.5,-107.4) 3(140.5,-107.4) 4(140.5,93.4)
  silkscreen extent -167,-142 133,128
US1M [mil]
  rect 70.9x63.8 smd mask+2: 1(180.1,-1) 2(-1,-1)
  silkscreen extent -31,-58 196,56

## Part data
C1 C2 C3 C4 C5 C6 C9 C12 C14 C15 C16 C17 C18 C19 C20 C21 C22 C23 C24 C25 C26 C27 C28 C29 C30 C31 C32 C33 C34 C35 C36 C37 C38 C39 C40 C41 C42 C43 C44 C45 C46 C47 C48 C49 C50 C51 C52 C53 C54 C61 C65 C67 C69 C70 C71 C79 C80: library part 贴片电容
C7 C8 C10 C11 C13 C64 C66: library part 贴片电解电容
C74 C75 C76 C77 C78: library part 1n
D4: library part 1N4007
D5 D6: library part SK-33
F1: library part SQT6.30M
F4 R1 R2 R3 R4 R5 R6 R7 R8 R9 R10 R11 R12 R13 R14 R15 R16 R17 R18 R19 R20 R21 R22 R23 R24 R25 R26 R27 R28 R29 R30 R31 R32 R33 R34 R35 R36 R37 R38 R39 R40 R41 R42 R43 R44 R45 R46 R47 R48 R49 R50 R51 R52 R53 R54 R55 R56: library part 贴片电阻
J1: library part 2P插针
L2 L3 L4 L5 L6: library part 贴片电感
U14: library part INA180A1

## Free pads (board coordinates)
  rect 2.2x1.8 on Top Solder: 0(-19.038,20.17) 0(-12.138,20.17)
  rect 2x2 smd far side: 0(-12.029,22.907) 1(-9.53,22.907) 2(-7.031,22.907) 3(-4.529,22.907) 4(-2.029,22.907)
  oval 1.2x2.2 on Top Solder: 5(-12.749,-41.447) 5(-12.749,-37.747) 5(-4.11,-41.447) 5(-4.11,-37.747)
  oval 1.2x2.2 on Bottom Solder: 5(-12.749,-41.447) 5(-12.749,-37.747) 5(-4.11,-41.447) 5(-4.11,-37.747)
  round 3.1 hole 2: ""(-93.758,22.474) ""(-69.248,-40.829) ""(2.014,22.522) ""(2.062,-40.829)

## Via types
v1: diameter 0.45, hole 0.3, Top Layer to Bottom Layer, 389 vias

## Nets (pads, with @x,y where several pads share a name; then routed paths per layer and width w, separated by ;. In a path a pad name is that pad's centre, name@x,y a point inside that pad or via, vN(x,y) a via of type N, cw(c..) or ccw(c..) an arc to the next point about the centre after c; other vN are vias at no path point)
5V: C42.1 C43.1 C44.1 C79.1 C80.1 L5.2 R29.1 U8.1 U8.3 U10.1 U10.3 | length 61.4
  Top Layer w0.5: L5.2@-57.341,-33.379 -55.867,-33.379 -54.86,-34.386 C43.1@-54.86,-36.668 -52.606,-36.668 C42.1@-52.503,-36.77 -52.503,-35.255 ; L5.2@-56.988,-33.733 cw(c-56.134,-34.586) -56.134,-33.379 cw(c-56.134,-32.172) L5.2@-56.988,-33.026 ; C43.1@-55.037,-36.491 ccw(c-55.465,-36.063) -54.86,-36.063 ccw(c-54.256,-36.063) C43.1@-54.683,-36.491 ; C43.1@-54.409,-36.845 cw(c-53.981,-37.272) -53.981,-36.668 cw(c-53.981,-36.063) C43.1@-54.409,-36.491 ; -53.406,-36.668 cw(c-53.406,-37.622) C42.1@-52.731,-36.947 ; C44.1@-53.015,-34.743 -52.503,-35.255 ; C44.1@-52.68,-34.481 ccw(c-51.975,-34.727) -52.503,-35.255 ; C42.1@-52.68,-36.593 ccw(c-53.108,-36.166) -52.503,-36.166 ccw(c-51.899,-36.166) C42.1@-52.326,-36.593 ; C44.1@-52.639,-34.472 cw(c-52.967,-34.8) C44.1@-52.503,-34.8 ; -52.503,-35.265 cw(c-51.758,-35.265) C44.1@-52.225,-34.684 ; C44.1@-52.205,-34.666 cw(c-51.778,-35.094) -51.778,-34.489 cw(c-51.778,-33.885) C44.1@-52.205,-34.312 ; C79.1@-49.605,-36.593 ccw(c-50.033,-36.166) -49.428,-36.166 ccw(c-48.824,-36.166) C79.1@-49.251,-36.593 ; v1(-49.428,-29.595) -49.364,-29.659 U10.1@-47.431,-29.659 -46.312,-29.659 -46.044,-29.928 -46.044,-31.298 -46.305,-31.559 U10.3@-47.431,-31.559 ; C79.1@-49.201,-36.947 cw(c-48.773,-37.375) -48.773,-36.77 cw(c-48.773,-36.166) C79.1@-49.201,-36.593 ; C80.1@-49.201,-29.418 ccw(c-48.618,-28.835) -48.618,-29.659 ; U8.3@-47.431,-38.666 -46.495,-38.666 -46.041,-38.213 -46.041,-37.008 -46.283,-36.766 U8.1@-47.431,-36.766 -47.435,-36.77 C79.1@-49.428,-36.77 -49.428,-35.166 -50.105,-34.489 v1(-52.657,-34.489) -52.503,-34.643 -52.503,-35.255
  POWER w0.5: v1(-52.657,-34.489) -50.222,-34.489 -49.428,-33.696 v1(-49.428,-29.595)
  Bottom Layer w0.5: v1(-56.375,-41.129) -55.609,-41.895 -51.521,-41.895 -50.778,-41.152 -50.778,-35.037 -51.326,-34.489 v1(-52.657,-34.489)
12V: C1.1 C4.1 C7.1 C8.1 C9.1 F4.1 Q1.2 R4.1 R14.1 R17.1 | length 304.6
  Top Layer w0.5: R14.1@-46.775,-10.861 -41.717,-10.861 ; R14.1@-46.598,-11.038 cw(c-46.171,-11.465) -46.171,-10.861 cw(c-46.171,-10.257) R14.1@-46.598,-10.684 ; -42.823,-10.904 -42.823,-10.926 -42.257,-11.492 ; R17.1@-42.434,-14.743 ccw(c-42.861,-14.315) -42.257,-14.315 ccw(c-41.652,-14.315) R17.1@-42.08,-14.743 ; R17.1@-42.257,-14.92 -42.257,-11.492 ; -42.257,-10.87 -42.257,-11.492 ; Q1.2@-41.695,7.654 cw(c-51.582,-3.641) -36.571,-3.641 ; Q1.2@-41.366,8.03 cw(c-50.617,-2.539) -36.571,-2.539 ; Q1.2@-41.036,8.406 cw(c-49.653,-1.437) -36.571,-1.437 ; Q1.2@-40.707,8.782 cw(c-48.688,-0.335) -36.571,-0.335 ; Q1.2@-40.418,6.543 -40.39,6.543 -39.522,5.676 ; Q1.2@-40.378,9.158 cw(c-47.723,0.767) -36.571,0.767 ; Q1.2@-40.312,6.527 cw(c-40.406,5.649) -39.522,5.649 cw(c-38.331,5.649) Q1.2@-38.79,6.748 ; Q1.2@-40.259,7.025 cw(c-40.346,6.205) -39.522,6.205 ; Q1.2@-40.048,9.535 cw(c-46.758,1.869) -36.571,1.869 ; Q1.2@-39.982,9.61 v1(-39.752,9.61) ; Q1.2@-39.777,9.611 ccw(c-38.974,9.59) Q1.2@-39.557,9.037 ; Q1.2@-39.751,9.635 cw(c-39.782,8.855) Q1.2@-39.208,9.385 ; Q1.2@-39.749,9.635 cw(c-39.779,9.38) Q1.2@-39.522,9.38 ; Q1.2@-39.735,9.628 cw(c-40.247,9.116) Q1.2@-39.522,9.116 ; Q1.2@-39.719,9.911 cw(c-45.793,2.972) -36.571,2.972 ; Q1.2@-39.451,12.156 ccw(c-38.734,15.589) -36.253,13.109 ; Q1.2@-39.39,10.287 cw(c-44.828,4.074) -36.571,4.074 ; -39.374,-5.806 cw(c-37.898,-5.806) v1@-38.942,-4.763 ; -39.374,-3.755 ccw(c-37.898,-3.755) v1@-38.942,-4.798 ; -39.374,-1.777 cw(c-37.964,-1.777) v1@-38.961,-0.78 ; -39.374,0.182 ccw(c-37.964,0.182) v1@-38.961,-0.815 ; Q1.2@-39.349,12.645 ccw(c-38.508,16.671) -35.6,13.763 ; Q1.2@-39.06,10.663 cw(c-43.864,5.176) -36.571,5.176 ; Q1.2@-38.731,11.04 cw(c-42.899,6.278) -36.571,6.278 ; C8.1@-38.425,-7.425 cw(c-39.364,-8.364) -38.036,-8.364 cw(c-36.708,-8.364) C8.1@-37.647,-7.425 ; Q1.2@-38.402,11.416 cw(c-41.934,7.38) -36.571,7.38 ; Q1.2@-38.072,11.792 cw(c-40.969,8.483) -36.571,8.483 ; C8.1@-38.036,-7.036 -38.036,-8.026 ; Q1.2@-37.743,12.168 cw(c-40.004,9.585) -36.571,9.585 ; Q1.2@-37.49,12.699 Q1.2@-36.664,12.699 ; Q1.2@-37.414,12.544 cw(c-39.039,10.687) -36.571,10.687 ; Q1.2@-37.401,9.923 cw(c-33.665,10.376) -36.326,13.037 ; -37.315,-8.026 -37.336,-8.026 ; Q1.2@-36.904,9.983 cw(c-32.369,10.533) -35.6,13.763 ; -36.873,-5.023 -36.873,-5.071 -36.571,-5.071 ; R4.1@-36.78,20.118 -35.599,18.937 -35.599,13.763 ; R4.1@-36.73,19.868 cw(c-36.73,19.386) R4.1@-36.389,19.727 ; R4.1@-36.479,20.118 ccw(c-35.752,20.118) -36.266,19.604 ; -36.147,-5.691 -36.571,-5.691 -36.571,-5.071 ; -36.143,-8.026 ccw(c-36.143,-4.269) F4.1@-33.464,-6.904 ; -34.95,-8.026 ccw(c-34.95,-5.443) F4.1@-33.108,-7.255 ; F4.1@-33.821,-6.553 cw(c-37.336,-3.095) -37.336,-8.026 ; -33.757,-8.026 ccw(c-33.757,-6.617) F4.1@-32.752,-7.605 ; -42.257,-11.492 -41.717,-10.952 -41.717,-10.861 ; -41.717,-10.861 -39.267,-10.861 -38.036,-9.63 -38.036,-8.726 ; v1(-39.752,9.61) -39.522,9.61 -39.522,5.676 ; v1(-39.752,9.61) Q1.2@-36.664,12.699 ; -39.522,5.676 -39.522,-8.026 -39.374,-8.026 ; -39.522,5.676 -39.374,5.527 -39.374,-8.026 ; -39.374,-8.026 -38.736,-8.026 ; -38.736,-8.026 -38.036,-8.726 ; -38.736,-8.026 -38.036,-8.026 ; C8.1@-38.327,-7.503 cw(c-38.653,-8.026) -38.036,-8.026 ; C8.1@-38.327,-7.503 cw(c-38.653,-8.026) -38.036,-8.026 ; C8.1@-38.327,-7.503 cw(c-38.653,-8.026) -38.036,-8.026 ; C8.1@-38.327,-7.503 cw(c-38.653,-8.026) -38.036,-8.026 ; -38.036,-8.726 -38.036,-8.026 ; -38.036,-8.726 -37.336,-8.026 ; -38.036,-8.026 cw(c-37.419,-8.026) C8.1@-37.745,-7.503 ; -38.036,-8.026 cw(c-37.419,-8.026) C8.1@-37.745,-7.503 ; -38.036,-8.026 cw(c-37.419,-8.026) C8.1@-37.745,-7.503 ; -38.036,-8.026 cw(c-37.419,-8.026) C8.1@-37.745,-7.503 ; -38.036,-8.026 -37.336,-8.026 ; -37.336,-8.026 -31.673,-8.026 -31.673,-5.071 -35.707,-5.071 ; Q1.2@-36.664,12.699 -36.571,12.792 ; Q1.2@-36.664,12.699 -36.571,12.699 ; -36.571,-5.071 -36.571,-4.333 ; -36.571,-5.071 -36.288,-5.071 ; -36.571,-4.333 -36.571,12.699 ; -36.571,-4.333 -36.288,-4.575 ; -36.571,12.699 -36.571,12.792 ; -36.571,12.699 -36.288,12.699 -36.288,-4.575 ; -36.571,12.791 cw(c-37.887,14.107) -38.673,12.42 ccw(c-37.887,14.107) -36.571,12.791 ; -36.571,12.791 ccw(c-35.109,11.33) -37.059,10.642 cw(c-35.109,11.33) -36.571,12.791 ; -36.571,12.792 -35.599,13.763 ; -36.288,-5.071 -36.288,-4.575 ; -36.288,-5.071 -35.707,-5.071 ; -36.288,-4.575 -35.707,-5.071
  Bottom Layer w0.5: C1.1@-52.246,21.895 cw(c-52.246,20.326) -51.136,21.435 cw(c-50.027,22.545) C1.1@-51.596,22.545 ; C1.1@-52.246,22.545 -49.818,20.117 -44.778,20.117 -43.972,19.312 -43.972,15.257 -43.158,14.443 -40.623,14.443 -39.752,13.571 v1(-39.752,9.61)
  other v1: -38.924,-4.78 -38.943,-0.797
A3.3V: C45.2 C46.2 C49.1 C53.1 C71.2 U10.5 U11.8 U12.8 U14.5 | length 91.8
  Top Layer w0.2: v1@-30.219,-14.732 ccw(c-30.433,-14.519) -30.131,-14.519 ccw(c-29.829,-14.519) v1@-30.042,-14.732 ; v1(-30.131,-14.821) -30.131,-9.606 -28.66,-8.136 -21.535,-8.136 -20.95,-7.55 C53.1@-19.726,-7.55 v1@-19.726,-8.627 ; C71.2@-28.325,-20.487 ccw(c-29.016,-19.796) -28.039,-19.796 ; C71.2@-28.184,-20.628 ccw(c-28.533,-20.279) -28.039,-20.279 ; U14.5@-28.163,-19.372 cw(c-28.461,-19.671) -28.039,-19.671 cw(c-27.616,-19.671) U14.5@-27.915,-19.372 ; C71.2@-28.085,-20.727 cw(c-27.795,-21.017) -27.795,-20.607 cw(c-27.795,-20.197) C71.2@-28.085,-20.487 ; C71.2@-28.061,-20.516 cw(c-27.925,-20.43) -28.039,-20.316 ; U14.5@-28.039,-19.024 -28.039,-20.316 ; v1@-26.847,-20.695 ccw(c-27.061,-20.909) -27.061,-20.607 ccw(c-27.061,-20.305) v1@-26.847,-20.519 ; v1@-26.747,-20.618 v1(-26.759,-20.607) C71.2@-28.33,-20.607 -28.039,-20.316 ; U11.8@-21.677,-9.364 ccw(c-22.018,-9.023) -21.535,-9.023 ccw(c-21.053,-9.023) U11.8@-21.394,-9.364 ; U11.8@-21.535,-10.005 -21.535,-8.989 -21.201,-8.655 -19.754,-8.655 v1@-19.726,-8.627 ; -20.073,-8.655 ccw(c-20.073,-8.279) -19.808,-8.545 ccw(c-20.006,-8.347) -19.726,-8.347 ; -19.969,-8.655 cw(c-19.969,-8.883) v1@-19.808,-8.722 ; C53.1@-19.846,-7.796 cw(c-20.136,-8.086) -19.726,-8.086 cw(c-19.315,-8.086) C53.1@-19.605,-7.796 ; C53.1@-19.846,-7.671 ccw(c-20.136,-7.961) -20.136,-7.55 ccw(c-20.136,-7.14) C53.1@-19.846,-7.43 ; -19.726,-8.316 ccw(c-19.402,-8.316) v1@-19.631,-8.545 ; v1(-19.719,-8.633) v1@-19.726,-8.627 ; U12.8@-15.315,-9.322 U12.8@-15.3,-9.337 -15.3,-10.646 v1(-14.858,-11.088) ; v1@-14.983,-11.088 ccw(c-15.285,-11.088) -15.072,-10.874 ccw(c-14.858,-10.661) v1@-14.858,-10.963 ; C49.1@-12.886,-7.796 cw(c-13.176,-8.086) -12.766,-8.086 cw(c-12.356,-8.086) C49.1@-12.646,-7.796 ; v1@-12.854,-8.45 ccw(c-13.068,-8.236) -12.766,-8.236 ccw(c-12.464,-8.236) v1@-12.678,-8.45 ; v1@-12.775,-8.547 v1(-12.766,-8.538) C49.1@-12.766,-7.55
  Top Layer w0.5: U10.5@-44.631,-29.659 -40.651,-29.659 C45.2@-40.587,-29.595 v1(-35.729,-29.595) v1@-35.724,-29.6 ; -43.618,-29.659 ccw(c-43.618,-28.835) C46.2@-43.035,-29.418 ; C46.2@-42.579,-29.418 ccw(c-41.996,-28.835) -41.996,-29.659 ; -41.398,-29.659 ccw(c-41.398,-28.835) C45.2@-40.815,-29.418 ; C45.2@-40.359,-29.772 cw(c-39.932,-30.2) -39.932,-29.595 cw(c-39.932,-28.991) C45.2@-40.359,-29.418
  POWER w0.2: v1@-35.817,-29.684 ccw(c-36.03,-29.897) -36.03,-29.595 ccw(c-36.03,-29.293) v1@-35.817,-29.507 ; v1(-35.729,-29.595) -36.731,-29.595 -37.149,-29.177 -37.149,-18.196 -36.162,-17.21 -27.385,-17.21 -26.759,-17.836 v1(-26.759,-20.607) ; v1@-30.219,-14.909 cw(c-30.433,-15.123) -30.131,-15.123 cw(c-29.829,-15.123) v1@-30.042,-14.909 ; v1(-30.131,-14.821) -30.131,-17.17 -30.119,-17.182 ; v1@-26.847,-20.519 ccw(c-27.061,-20.305) -26.759,-20.305 ccw(c-26.457,-20.305) v1@-26.671,-20.519 ; v1(-14.858,-11.088) -13.312,-11.088 -12.766,-10.542 v1(-12.766,-8.538) ; v1@-14.77,-11.176 cw(c-14.557,-11.389) -14.557,-11.088 cw(c-14.557,-10.786) v1@-14.77,-10.999 ; v1@-12.854,-8.627 cw(c-13.068,-8.84) -12.766,-8.84 cw(c-12.464,-8.84) v1@-12.678,-8.627
  Bottom Layer w0.2: v1(-19.719,-8.633) -19.276,-8.19 -16.071,-8.19 -15.112,-7.231 -13.265,-7.231 -12.766,-7.73 v1(-12.766,-8.538) ; v1@-19.719,-8.508 ccw(c-19.719,-8.207) -19.506,-8.42 ccw(c-19.293,-8.633) v1@-19.594,-8.633 ; v1@-12.854,-8.45 ccw(c-13.068,-8.236) -12.766,-8.236 ccw(c-12.464,-8.236) v1@-12.678,-8.45
ADC_IIN: C70.1 R54.2 U12.6 | length 20.2
  Top Layer w0.2: R54.2@-26.36,-18.057 -25.978,-18.057 ; R54.2@-26.234,-18.17 cw(c-25.978,-18.401) -25.978,-18.057 ; R54.2@-26.234,-17.943 ccw(c-25.978,-17.712) -25.978,-18.057 ; C70.1@-25,-16.784 ccw(c-25,-16.071) -24.496,-16.575 ; v1@-17.108,-16.167 ccw(c-17.321,-16.38) -17.321,-16.078 ccw(c-17.321,-15.776) v1@-17.108,-15.99 ; v1(-17.019,-16.078) -23.999,-16.078 C70.1@-25,-17.079 -25.978,-18.057 ; v1@-16.388,-13.143 ccw(c-16.601,-12.93) -16.299,-12.93 ccw(c-15.998,-12.93) v1@-16.211,-13.143 ; U12.6@-16.299,-9.337 v1(-16.299,-13.232) v1@-16.295,-13.236
  Bottom Layer w0.2: v1(-17.019,-16.078) -16.299,-15.358 v1(-16.299,-13.232) ; v1@-17.019,-15.953 ccw(c-17.019,-15.651) -16.806,-15.865 ccw(c-16.592,-16.078) v1@-16.894,-16.078 ; v1@-16.388,-13.32 cw(c-16.601,-13.534) -16.299,-13.534 cw(c-15.998,-13.534) v1@-16.211,-13.32
ADC_IOUT: C57.2 R45.2 U12.5 | length 27.8
  Top Layer w0.2: R45.2@-17.632,-26.528 -16.147,-26.528 v1(-16.147,-25.115) ; R45.2@-17.499,-26.648 cw(c-17.208,-26.938) -17.208,-26.528 cw(c-17.208,-26.117) R45.2@-17.499,-26.407 ; -16.695,-26.528 cw(c-16.695,-26.968) C57.2@-16.383,-26.657 ; -16.652,-26.528 ccw(c-16.652,-26.148) C57.2@-16.383,-26.416 ; v1@-16.381,-6.439 ccw(c-16.578,-6.242) -16.3,-6.242 ; -16.3,-6.209 ccw(c-15.975,-6.209) v1@-16.204,-6.439 ; U12.5@-16.3,-4.637 -16.3,-6.521 v1(-16.293,-6.528) ; C57.2@-16.258,-26.416 ccw(c-16.527,-26.148) -16.147,-26.148 ; v1@-16.235,-25.204 cw(c-16.449,-25.417) -16.147,-25.417 cw(c-15.845,-25.417) v1@-16.058,-25.204 ; -16.147,-26.105 ccw(c-15.706,-26.105) C57.2@-16.018,-26.416
  POWER w0.2: v1@-16.293,-6.653 cw(c-16.293,-7.077) -15.993,-6.777 ; v1(-16.293,-6.528) -16.242,-6.528 -15.395,-7.375 -15.395,-23.732 -16.147,-24.484 v1(-16.147,-25.115) ; v1@-16.235,-25.027 ccw(c-16.449,-24.814) -16.147,-24.814 ccw(c-15.845,-24.814) v1@-16.058,-25.027
ADC_VIN: C52.1 D6.1 R41.1 U12.7 | length 14.7
  Top Layer w0.2: R41.1@-20.696,-1.121 -19.471,-1.121 C52.1@-19.359,-1.234 -17.974,-1.234 -17.61,-1.598 D6.1@-17.61,-1.786 -17.61,-6.21 -15.8,-8.021 U12.7@-15.8,-9.337 ; R41.1@-20.576,-1.242 cw(c-20.286,-1.532) -20.286,-1.121 cw(c-20.286,-0.711) R41.1@-20.576,-1.001 ; -19.8,-1.121 ccw(c-19.8,-0.667) C52.1@-19.479,-0.988 ; -19.738,-1.121 cw(c-19.738,-1.488) C52.1@-19.479,-1.229 ; C52.1@-19.238,-1.354 cw(c-18.948,-1.644) -18.948,-1.234 cw(c-18.948,-0.823) C52.1@-19.238,-1.113 ; -17.839,-1.369 ccw(c-17.61,-1.14) D6.1@-17.61,-1.463 ; D6.1@-17.823,-1.385 cw(c-18.029,-1.591) D6.1@-17.737,-1.591 ; D6.1@-17.7,-2.071 cw(c-17.918,-2.289) -17.61,-2.289 cw(c-17.302,-2.289) D6.1@-17.52,-2.071
ADC_VOUT: C47.2 D5.1 R34.1 U12.4 | length 25.2
  Top Layer w0.16: R34.1@-20.63,-13.426 -19.414,-13.426 C47.2@-19.301,-13.539 ; R34.1@-20.496,-13.561 cw(c-20.172,-13.885) -20.172,-13.426 cw(c-20.172,-12.968) R34.1@-20.496,-13.292 ; -19.791,-13.426 ccw(c-19.791,-12.924) C47.2@-19.436,-13.279 ; -19.729,-13.426 cw(c-19.729,-13.841) C47.2@-19.436,-13.548
  Top Layer w0.2: C47.2@-19.301,-13.539 -18.074,-13.539 -17.662,-13.951 D5.1@-17.662,-14.091 -14.142,-14.091 -13.566,-13.515 -13.566,-2.957 -13.769,-2.753 -15.554,-2.753 -15.8,-2.999 U12.4@-15.8,-4.637 ; C47.2@-19.181,-13.659 cw(c-18.891,-13.949) -18.891,-13.539 cw(c-18.891,-13.128) C47.2@-19.181,-13.418 ; -17.973,-13.64 ccw(c-17.662,-13.328) D5.1@-17.662,-13.769 ; D5.1@-17.572,-14.181 cw(c-17.354,-14.399) -17.354,-14.091 cw(c-17.354,-13.783) D5.1@-17.572,-14.001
